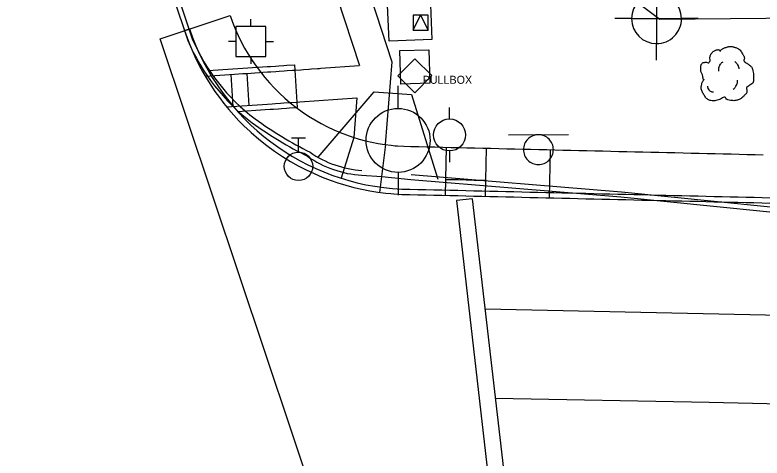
# Model space of a CAD drawing. Extents: x 2145380 to 2157287, y 139568 to 149130.
# Drawn here: x 2147327.9 to 2147421.2, y 143182.8 to 143238.1 of the extents above; entities that cross this region are included whole.
import ezdxf

# ---------------------------------------------------------------- set-up
doc = ezdxf.new("R2010")
doc.units = 0
for name, color, linetype in [('Default', 7, 'Continuous'), ('PR_PREVIOUSLY CONSTRUCTED', 7, 'Continuous'), ('SURV_Benchmark', 7, 'Continuous'), ('TOPO_Asphalt', 7, 'Continuous'), ('TOPO_Concrete', 7, 'Continuous'), ('TOPO_Curb Back', 7, 'Continuous'), ('TOPO_Misc', 7, 'Continuous'), ('TOPO_Misc Line', 7, 'Continuous'), ('TOPO_Power Pole', 7, 'Continuous'), ('TOPO_Power Pullbox', 7, 'Continuous'), ('TOPO_Sidewalk', 7, 'Continuous'), ('TOPO_Sign', 7, 'Continuous'), ('TOPO_Traffic Signal', 7, 'Continuous'), ('TOPO_Tree', 7, 'Continuous'), ('TOPO_Water Valve', 7, 'Continuous')]:
    doc.layers.add(name, color=color, linetype=linetype)

# ---------------------------------------------------------------- blocks, each defined once
blk = doc.blocks.new('POWPOL')
at = {"layer": 'TOPO_Power Pole'}
for p, q in [((0, 10.16), (0, 17.34)), ((0, -10.16), (0, -17.34))]:
    blk.add_line(p, q, dxfattribs=at)
blk.add_circle((0, 0), 10.16, dxfattribs=at)
blk = doc.blocks.new('TRFSIG')
at = {"layer": 'TOPO_Traffic Signal'}
for p, q in [((0.04, 4.66), (0.04, 7.04)), ((-4.7, -0.09), (-7.08, -0.09)), ((4.79, -0.09), (7.17, -0.09)), ((0.04, -4.83), (0.04, -7.22))]:
    blk.add_line(p, q, dxfattribs=at)
blk.add_lwpolyline([(-4.7, -4.85), (4.81, -4.83), (4.79, 4.67), (-4.72, 4.66), (-4.7, -4.85)], dxfattribs=at)
blk = doc.blocks.new('TREE')
at = {"layer": 'TOPO_Tree'}
for points in [[(-3.49, 17.6), (-3.07, 18.27), (-2.58, 18.8), (-1.9, 19.19), (-1.05, 19.68), (-0.19, 19.96), (0.74, 20.24), (1.62, 20.51), (2.51, 20.82), (3.39, 20.77), (4.1, 20.73), (4.8, 20.47), (5.51, 20.24), (6.43, 19.95), (7.32, 19.73), (8.15, 19.19), (9.36, 18.4), (10.02, 17.21), (10.8, 16.01), (11.24, 15.33), (11.58, 14.62), (11.86, 13.89), (12.17, 13.08), (11.37, 12.02), (11.86, 11.25), (12, 11.03), (12.18, 10.86), (12.39, 10.72), (12.91, 10.35), (13.45, 10.02), (13.97, 9.66), (14.7, 9.16), (15.41, 8.68), (16.09, 8.07), (16.7, 7.53), (16.93, 6.73), (17.15, 5.95), (17.59, 4.38), (17.71, 2.77), (17.68, 1.19), (17.65, -0.25), (17.83, -2.22), (16.62, -3.04), (15.47, -3.83), (14.31, -4.58), (13.16, -5.35)], [(-14.07, -0.4), (-14.17, 0.5), (-14.37, 1.38), (-14.6, 2.25), (-14.84, 3.17), (-15.47, 3.96), (-15.66, 4.9), (-15.8, 5.59), (-15.71, 6.31), (-15.66, 7.01), (-15.6, 7.91), (-15.72, 8.8), (-15.13, 9.66), (-14.62, 10.42), (-13.76, 10.49), (-13.02, 10.72), (-12.18, 10.98), (-11.06, 10), (-10.37, 10.72), (-9.4, 11.74), (-10.29, 13.28), (-9.84, 14.42), (-9.56, 15.15), (-9.32, 15.89), (-8.78, 16.54), (-8.18, 17.26), (-7.5, 17.68), (-6.67, 18.13), (-6.14, 18.41), (-5.61, 18.61), (-5.08, 18.66), (-4.55, 18.71), (-4.02, 18.54), (-3.49, 18.13)], [(-4.21, 5.09), (-4.46, 6.09), (-4.3, 7.21), (-3.84, 8.21), (-3.33, 9.34), (-2.71, 10.27), (-1.64, 10.97)], [(5.89, 11.15), (6.5, 10.68), (6.96, 10.17), (7.36, 9.5), (7.93, 8.56), (8.31, 7.6), (8.46, 6.56)], [(13.16, -5.34), (13.25, -5.81), (13.36, -6.28), (13.45, -6.75), (13.76, -8.52), (12.24, -10.03), (10.8, -11.51), (9.98, -12.34), (9.13, -12.77), (8.15, -13.1), (5.97, -13.83), (3.32, -13.56), (1.27, -13.1), (0.49, -12.92), (-0.06, -11.44), (-0.84, -11.51), (-2.04, -11.61), (-3.28, -12.78), (-4.55, -13.1), (-6.06, -13.47), (-7.77, -14.03), (-9.31, -13.62), (-11.36, -13.09), (-12.84, -11.41), (-14.07, -9.39), (-15.32, -7.35), (-15.61, -5.13), (-15.13, -3.04), (-14.87, -1.89), (-13.91, -0.75), (-13.54, 0.13)], [(-11.38, -4.46), (-11.47, -5.41), (-11.03, -6.32), (-10.09, -7.22), (-9.3, -7.97), (-8.49, -8.26), (-7.7, -8.14)], [(4.79, -6.29), (5.71, -5.66), (6.3, -4.92), (6.81, -3.91), (7.36, -2.81), (7.63, -1.7), (7.54, -0.6)]]:
    blk.add_open_spline(points, degree=3, dxfattribs=at)
blk = doc.blocks.new('pulbox')
at = {"layer": 'Default'}
blk.add_lwpolyline([(-5.38, -0.01), (-0.02, 5.42), (5.4, 0.06), (0.05, -5.36), (-5.38, -0.01)], dxfattribs=at)
blk.add_text('PULLBOX', height=2.54, dxfattribs=at).set_placement((2.54, -2.54))
blk = doc.blocks.new('WATVAL')
at = {"layer": 'Default'}
for p, q in [((-2.25, 9), (2.25, 9)), ((0, 4.5), (0, 9))]:
    blk.add_line(p, q, dxfattribs=at)
blk.add_circle((0, 0), 4.5, dxfattribs=at)
blk = doc.blocks.new('BM')
at = {"layer": 'SURV_Benchmark'}
for p, q in [((0, 2.493), (0, 4.153)), ((-2.493, 0), (-4.157, 0)), ((4.157, 0), (2.493, 0)), ((0, -4.157), (0, -2.493))]:
    blk.add_line(p, q, dxfattribs=at)
for points in [[(-0.002, 2.495), (0, 2.493), (0, 0), (2.493, 0), (2.493, 0), (2.494, 0.002)], [(-0.002, 2.495), (0, 2.493), (0, 0), (2.493, 0), (2.493, 0), (2.494, 0.002), (2.494, 0.002)], [(-2.496, -0.001), (-2.493, 0), (0, 0), (0, -2.493), (0.001, -2.495)], [(-2.496, -0.001), (-2.493, 0), (0, 0), (0, -2.493), (0.001, -2.495)]]:
    blk.add_lwpolyline(points, dxfattribs=at)
for centre, start, end in [((0.001, -0.001), 90.06381, 180.00681), ((-0.002, -0.001), 0.06381, 90.00681), ((-0.002, -0.001), 0.06381, 90.00681), ((0.001, 0.001), 180.06381, 270.00681), ((0.001, 0.001), 180.06381, 270.00681), ((0.001, -0.001), 269.94719, 359.99266)]:
    blk.add_arc(centre, 2.496, start, end, dxfattribs=at)

msp = doc.modelspace()

# ---------------------------------------------------------------- linework, layer by layer
at = {"layer": 'PR_PREVIOUSLY CONSTRUCTED'}
for p, q in [((2147371.241, 143243.57), (2147374.948, 143232.28)), ((2147367.44, 143242.322), (2147370.897, 143231.795)), ((2147349.041, 143236.162), (2147349.673, 143236.374)), ((2147363.151, 143226.576), (2147362.807, 143231.898)), ((2147374.948, 143232.28), (2147374.125, 143221.932)), ((2147355.126, 143226.703), (2147354.868, 143230.695)), ((2147357.122, 143226.832), (2147356.864, 143230.824)), ((2147370.577, 143227.771), (2147370.184, 143222.83)), ((2147370.184, 143222.83), (2147368.621, 143217.726)), ((2147373.443, 143215.964), (2147374.205, 143221.922)), ((2147381.627, 143215.59), (2147381.765, 143221.596)), ((2147386.625, 143215.475), (2147386.763, 143221.481)), ((2147394.623, 143215.291), (2147394.761, 143221.297))]:
    msp.add_line(p, q, dxfattribs=at)
for points in [[(2147378.896, 143136.918), (2147346.01, 143235.148), (2147354.738, 143238.07)], [(2147352.002, 143231.165), (2147358.786, 143231.622), (2147359.383, 143231.662), (2147359.798, 143231.69), (2147360.421, 143231.733), (2147360.81, 143231.759), (2147361.459, 143231.804), (2147361.822, 143231.829), (2147362.807, 143231.898)], [(2147366.082, 143231.462), (2147370.872, 143231.794)], [(2147351.625, 143230.485), (2147355.275, 143230.721), (2147355.794, 143230.755), (2147356.313, 143230.789), (2147356.807, 143230.821), (2147356.891, 143230.827), (2147357.351, 143230.858), (2147357.819, 143230.889), (2147358.39, 143230.927), (2147358.831, 143230.956), (2147359.428, 143230.997), (2147359.843, 143231.025), (2147360.467, 143231.068), (2147360.856, 143231.094), (2147361.505, 143231.139), (2147361.868, 143231.164), (2147362.543, 143231.211), (2147362.88, 143231.235), (2147363.581, 143231.284), (2147363.892, 143231.306), (2147364.576, 143231.355), (2147364.619, 143231.358), (2147364.904, 143231.378), (2147365.657, 143231.433), (2147365.916, 143231.451), (2147366.082, 143231.463)], [(2147354.304, 143226.648), (2147359.415, 143226.992), (2147360.012, 143227.032), (2147360.427, 143227.06), (2147361.05, 143227.103), (2147361.439, 143227.129), (2147362.088, 143227.174), (2147362.451, 143227.199), (2147363.126, 143227.246), (2147363.462, 143227.27), (2147370.577, 143227.771)], [(2147355.682, 143226.068), (2147359.131, 143226.3), (2147359.728, 143226.34), (2147360.143, 143226.368), (2147360.766, 143226.411), (2147361.154, 143226.437), (2147361.803, 143226.482), (2147362.166, 143226.507), (2147363.151, 143226.576)], [(2147362.955, 143226.597), (2147362.957, 143226.596), (2147363.743, 143226.022), (2147364.531, 143225.494), (2147365.319, 143225.009), (2147366.109, 143224.565), (2147366.899, 143224.158), (2147367.69, 143223.786), (2147368.482, 143223.449), (2147369.275, 143223.144), (2147370.069, 143222.87), (2147370.863, 143222.627), (2147371.658, 143222.413), (2147372.454, 143222.228), (2147373.25, 143222.072), (2147374.047, 143221.942), (2147374.844, 143221.84), (2147375.339, 143221.791), (2147375.351, 143221.79), (2147375.642, 143221.765), (2147376.441, 143221.717), (2147377.32, 143221.701), (2147378.32, 143221.678), (2147379.32, 143221.654), (2147380.32, 143221.631), (2147381.319, 143221.607), (2147382.319, 143221.584), (2147382.949, 143221.569), (2147383.319, 143221.56), (2147384.318, 143221.537), (2147385.318, 143221.513), (2147386.318, 143221.489), (2147387.318, 143221.466), (2147388.317, 143221.442), (2147389.317, 143221.419), (2147390.317, 143221.395), (2147391.316, 143221.372), (2147392.316, 143221.348), (2147393.316, 143221.325), (2147394.316, 143221.301), (2147395.315, 143221.278), (2147396.315, 143221.254), (2147397.315, 143221.23), (2147398.315, 143221.207), (2147399.314, 143221.183), (2147400.314, 143221.16), (2147401.314, 143221.136), (2147402.313, 143221.113), (2147403.313, 143221.089), (2147404.313, 143221.066), (2147405.313, 143221.042), (2147406.312, 143221.018), (2147407.312, 143220.995), (2147408.312, 143220.971), (2147409.311, 143220.948), (2147410.311, 143220.924), (2147411.311, 143220.901), (2147412.311, 143220.877), (2147413.31, 143220.854), (2147414.31, 143220.83), (2147415.31, 143220.807), (2147416.31, 143220.783), (2147417.309, 143220.759), (2147418.309, 143220.736), (2147419.309, 143220.712), (2147420.308, 143220.689), (2147421.308, 143220.665)], [(2147357.199, 143223.588), (2147357.356, 143223.445), (2147358.336, 143222.596), (2147359.318, 143221.815), (2147360.301, 143221.098), (2147361.286, 143220.438), (2147362.272, 143219.832), (2147363.259, 143219.276), (2147364.248, 143218.767), (2147365.237, 143218.302), (2147366.227, 143217.88), (2147367.219, 143217.499), (2147368.211, 143217.157), (2147369.204, 143216.853), (2147370.198, 143216.586), (2147371.193, 143216.355), (2147372.188, 143216.158), (2147373.185, 143215.997), (2147374.182, 143215.869), (2147374.801, 143215.807), (2147374.816, 143215.806), (2147375.18, 143215.775), (2147376.179, 143215.715), (2147377.179, 143215.695), (2147378.179, 143215.672), (2147379.178, 143215.648), (2147380.178, 143215.625), (2147381.178, 143215.601), (2147382.177, 143215.578), (2147382.807, 143215.563), (2147383.177, 143215.554), (2147384.177, 143215.531), (2147385.177, 143215.507), (2147386.176, 143215.483), (2147387.176, 143215.46), (2147388.176, 143215.436), (2147389.176, 143215.413), (2147390.175, 143215.389), (2147391.175, 143215.366), (2147392.175, 143215.342), (2147393.174, 143215.319), (2147394.174, 143215.295), (2147395.174, 143215.272), (2147396.174, 143215.248), (2147397.173, 143215.224), (2147398.173, 143215.201), (2147399.173, 143215.177), (2147400.173, 143215.154), (2147401.172, 143215.13), (2147402.172, 143215.107), (2147403.172, 143215.083), (2147404.171, 143215.06), (2147405.171, 143215.036), (2147406.171, 143215.012), (2147407.171, 143214.989), (2147408.17, 143214.965), (2147409.17, 143214.942), (2147410.17, 143214.918), (2147411.169, 143214.895), (2147412.169, 143214.871), (2147413.169, 143214.848), (2147414.169, 143214.824), (2147415.168, 143214.801), (2147416.168, 143214.777), (2147417.168, 143214.753), (2147418.168, 143214.73), (2147419.167, 143214.706), (2147420.167, 143214.683), (2147421.167, 143214.659), (2147422.166, 143214.636)], [(2147381.673, 143217.59), (2147382.224, 143217.577), (2147382.855, 143217.562), (2147383.224, 143217.553), (2147384.224, 143217.53), (2147385.225, 143217.506), (2147386.223, 143217.482), (2147386.671, 143217.472)], [(2147376.172, 143216.383), (2147377.195, 143216.363), (2147378.194, 143216.339), (2147379.194, 143216.316), (2147380.194, 143216.292), (2147381.193, 143216.269), (2147382.193, 143216.245), (2147382.823, 143216.23), (2147383.193, 143216.222), (2147384.193, 143216.198), (2147385.192, 143216.175), (2147386.192, 143216.151), (2147387.192, 143216.127), (2147388.192, 143216.104), (2147389.191, 143216.08), (2147390.191, 143216.057), (2147391.191, 143216.033), (2147392.19, 143216.01), (2147393.19, 143215.986), (2147394.19, 143215.963), (2147395.19, 143215.939), (2147396.189, 143215.915), (2147397.189, 143215.892), (2147398.189, 143215.868), (2147399.189, 143215.845), (2147400.188, 143215.821), (2147401.188, 143215.798), (2147402.188, 143215.774), (2147403.187, 143215.751), (2147404.187, 143215.727), (2147405.187, 143215.704), (2147406.187, 143215.68), (2147407.186, 143215.656), (2147408.186, 143215.633), (2147409.186, 143215.609), (2147410.185, 143215.586), (2147411.185, 143215.562), (2147412.185, 143215.539), (2147413.185, 143215.515), (2147414.184, 143215.492), (2147415.184, 143215.468), (2147416.184, 143215.444), (2147417.184, 143215.421), (2147418.183, 143215.397), (2147419.183, 143215.374), (2147420.183, 143215.35), (2147421.182, 143215.327), (2147422.182, 143215.303)]]:
    msp.add_lwpolyline(points, dxfattribs=at)
for radius, end in [(23.992, 232.71586), (29.333, 267.42741), (30, 227.44345)]:
    msp.add_arc((2147377.489, 143245.686), radius, 198.50992, end, dxfattribs=at)
at = {"layer": 'TOPO_Asphalt'}
msp.add_lwpolyline([(2147371.151, 143218.119), (2147373.707, 143217.967), (2147377.31, 143217.58)], dxfattribs=at)
at = {"layer": 'TOPO_Concrete'}
for points in [[(2147374.587, 143234.827), (2147374.364, 143240.291), (2147379.734, 143240.51), (2147379.957, 143235.046), (2147374.587, 143234.827)], [(2147379.546, 143233.776), (2147379.673, 143229.582), (2147376.078, 143229.473), (2147375.951, 143233.667), (2147379.546, 143233.776)]]:
    msp.add_lwpolyline(points, dxfattribs=at)
at = {"layer": 'TOPO_Curb Back'}
for points in [[(2147517.019, 143239.096), (2147482.377, 143238.343), (2147439.31, 143237.845), (2147408.436, 143237.554), (2147377.765, 143260.51), (2147364.559, 143270.237), (2147354.306, 143301.631), (2147333.229, 143365.364), (2147326.816, 143385.521), (2147326.462, 143411.357), (2147326.233, 143416.012)], [(2147293.796, 143402.608), (2147300.877, 143382.168), (2147313.769, 143342.423), (2147328.588, 143297.226), (2147344.021, 143251.185), (2147349.44, 143234.94)], [(2147294.365, 143402.799), (2147301.446, 143382.359), (2147314.34, 143342.61), (2147329.157, 143297.415), (2147344.59, 143251.375), (2147350.002, 143235.153)], [(2147377.31, 143217.58), (2147403.563, 143215.419), (2147433.326, 143212.43), (2147447.34, 143211.18), (2147492.585, 143210.09), (2147509.145, 143209.355)], [(2147377.359, 143218.178), (2147403.618, 143216.016), (2147433.382, 143213.027), (2147447.374, 143211.779), (2147492.605, 143210.689), (2147509.176, 143209.955)]]:
    msp.add_lwpolyline(points, dxfattribs=at)
for centre, radius, start, end in [((2147372.799, 143244.946), 25.411, 203.18897, 232.99221), ((2147372.799, 143244.946), 24.811, 203.24596, 232.97656), ((2147387.431, 143266.287), 50.674, 234.2978, 243.38591), ((2147387.431, 143266.287), 51.274, 234.2901, 243.33646), ((2147372.022, 143231.348), 13.273, 235.07004, 266.31699), ((2147372.022, 143231.348), 12.673, 234.87569, 266.31699)]:
    msp.add_arc(centre, radius, start, end, dxfattribs=at)
at = {"layer": 'TOPO_Misc'}
msp.add_lwpolyline([(2147377.602, 143236.21), (2147379.474, 143236.214), (2147379.471, 143238.085), (2147377.599, 143238.082), (2147377.602, 143236.21), (2147378.537, 143238.082), (2147379.474, 143236.214)], dxfattribs=at)
at = {"layer": 'TOPO_Misc Line'}
msp.add_lwpolyline([(2147389.926, 143172.788), (2147385.031, 143215.161), (2147383.036, 143214.93), (2147388.016, 143171.386)], close=True, dxfattribs=at)
for points in [[(2147386.618, 143201.423), (2147439.118, 143200.301), (2147482.851, 143199.426)], [(2147387.907, 143190.266), (2147414.568, 143189.752), (2147483.201, 143188.179)]]:
    msp.add_lwpolyline(points, dxfattribs=at)
at = {"layer": 'TOPO_Sidewalk'}
msp.add_lwpolyline([(2147365.731, 143220.346), (2147372.72, 143228.524), (2147377.389, 143228.178), (2147380.682, 143217.603)], dxfattribs=at)
at = {"layer": 'TOPO_Sign'}
for points in [[(2147389.502, 143223.168), (2147396.996, 143223.175)], [(2147393.252, 143223.168), (2147393.252, 143223.168)], [(2147391.385, 143221.3), (2147391.385, 143221.3)], [(2147395.12, 143221.3), (2147395.12, 143221.3)], [(2147393.252, 143219.432), (2147393.252, 143219.432)]]:
    msp.add_lwpolyline(points, dxfattribs=at)
for start, end in [(89.99996, 180.00004), (359.99996, 90.00004), (179.99996, 270.00004), (269.99996, 0.00004)]:
    msp.add_arc((2147393.252, 143221.3), 1.868, start, end, dxfattribs=at)

# ---------------------------------------------------------------- block references
at = {"layer": 'SURV_Benchmark', "xscale": 1.25, "yscale": 1.25}
msp.add_blockref('BM', (2147408.005, 143237.66), dxfattribs=at)
at = {"layer": 'TOPO_Power Pole'}
for p, xscale, yscale in [((2147375.723, 143222.456), 0.39370000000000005, 0.3937000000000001), ((2147382.141, 143223.133), 0.19685000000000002, 0.19685000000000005)]:
    msp.add_blockref('POWPOL', p, dxfattribs=dict(at, xscale=xscale, yscale=yscale))
at = {"layer": 'TOPO_Power Pullbox', "xscale": 0.39370000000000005, "yscale": 0.3937000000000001}
msp.add_blockref('pulbox', (2147377.801, 143230.524), dxfattribs=at)
at = {"layer": 'TOPO_Traffic Signal', "xscale": 0.39370000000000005, "yscale": 0.3937000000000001}
msp.add_blockref('TRFSIG', (2147357.322, 143234.84), dxfattribs=at)
at = {"layer": 'TOPO_Tree', "xscale": 0.19685000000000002, "yscale": 0.19685000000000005}
msp.add_blockref('TREE', (2147416.632, 143230.109), dxfattribs=at)
at = {"layer": 'TOPO_Water Valve', "xscale": 0.39370000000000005, "yscale": 0.3937000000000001}
msp.add_blockref('WATVAL', (2147363.282, 143219.22), dxfattribs=at)

doc.saveas('drawing.dxf')
